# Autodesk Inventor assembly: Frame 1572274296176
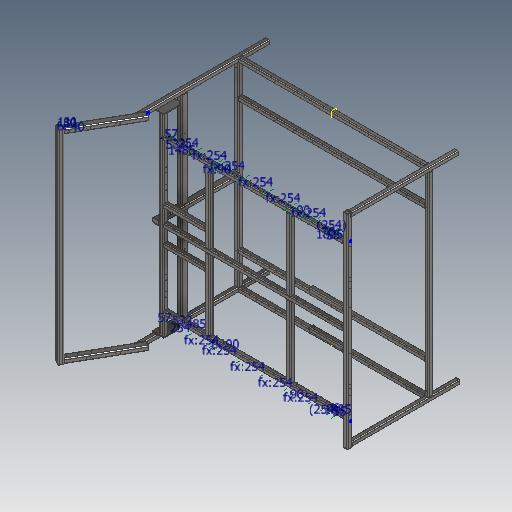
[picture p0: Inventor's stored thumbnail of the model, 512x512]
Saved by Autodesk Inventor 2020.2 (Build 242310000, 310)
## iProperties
_FrameDoc: Frame Assembly
_Version: 15.0.0
Part Number: Frame 1572274296176
Document SubType Name: Baugruppe
Designer: lutzd
Mass: 263385 g
Surface Area: 134163 cm^2
Volume: 33552.3 cm^3
Density: 7.85 g/cm^3
Mass: 263,385 kg
Dimensions: 2170x1958,9x2385 mm
Author: lutzd
Revision Number: -
Title: Frame 1572274296176
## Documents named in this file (26)
- D:\07 - DEMODATEN\OTX 2019 - Dataset - UPDATE - Dez2019\Designs\07-Packing machine\500586R\Frame\Frame 1572274296176.iam
- D:\07 - DEMODATEN\OTX 2019 - Dataset - UPDATE - Dez2019\Designs\07-Packing machine\500586R\Frame\Skeleton 1572274296222.ipt
- D:\07 - DEMODATEN\OTX 2019 - Dataset - UPDATE - Dez2019\Designs\07-Packing machine\500586R\Frame\_DS_FGM_DIN 50 x 50 x 5 1572274297625.ipt
- D:\07 - DEMODATEN\OTX 2019 - Dataset - UPDATE - Dez2019\Designs\07-Packing machine\500586R\Frame\_DS_FGM_DIN 50 x 50 x 5 1572274377820.ipt
- D:\07 - DEMODATEN\OTX 2019 - Dataset - UPDATE - Dez2019\Designs\07-Packing machine\500586R\Frame\_DS_FGM_DIN 70 x 50 x 5 1572274565859.ipt
- D:\07 - DEMODATEN\OTX 2019 - Dataset - UPDATE - Dez2019\Designs\07-Packing machine\500586R\Frame\_DS_FGM_DIN 70 x 50 x 5 1572274889356.ipt
- D:\07 - DEMODATEN\OTX 2019 - Dataset - UPDATE - Dez2019\Designs\07-Packing machine\500586R\Frame\ADSK-014384.ipt
- D:\07 - DEMODATEN\OTX 2019 - Dataset - UPDATE - Dez2019\Designs\07-Packing machine\500586R\Frame\ADSK-014383.ipt
- D:\07 - DEMODATEN\OTX 2019 - Dataset - UPDATE - Dez2019\Designs\07-Packing machine\500586R\Frame\ADSK-014381.ipt
- D:\07 - DEMODATEN\OTX 2019 - Dataset - UPDATE - Dez2019\Designs\07-Packing machine\500586R\Frame\ADSK-014379.ipt
- D:\07 - DEMODATEN\OTX 2019 - Dataset - UPDATE - Dez2019\Designs\07-Packing machine\500586R\Frame\ADSK-014380.ipt
- D:\07 - DEMODATEN\OTX 2019 - Dataset - UPDATE - Dez2019\Designs\07-Packing machine\500586R\Frame\ADSK-014382.ipt
- D:\07 - DEMODATEN\OTX 2019 - Dataset - UPDATE - Dez2019\Designs\07-Packing machine\500586R\Frame\ADSK-014378.ipt
- D:\07 - DEMODATEN\OTX 2019 - Dataset - UPDATE - Dez2019\Designs\07-Packing machine\500586R\Frame\ADSK-014377.ipt
- D:\07 - DEMODATEN\OTX 2019 - Dataset - UPDATE - Dez2019\Designs\07-Packing machine\500586R\Frame\ADSK-014376.ipt
- D:\07 - DEMODATEN\OTX 2019 - Dataset - UPDATE - Dez2019\Designs\07-Packing machine\500586R\Frame\ADSK-014375.ipt
- D:\07 - DEMODATEN\OTX 2019 - Dataset - UPDATE - Dez2019\Designs\07-Packing machine\500586R\Frame\ADSK-014374.ipt
- D:\07 - DEMODATEN\OTX 2019 - Dataset - UPDATE - Dez2019\Designs\07-Packing machine\500586R\Frame\ADSK-014372.ipt
- D:\07 - DEMODATEN\OTX 2019 - Dataset - UPDATE - Dez2019\Designs\07-Packing machine\500586R\Frame\ADSK-014385.ipt
- D:\07 - DEMODATEN\OTX 2019 - Dataset - UPDATE - Dez2019\Designs\07-Packing machine\Parts\ADSK-014388.ipt
- D:\07 - DEMODATEN\OTX 2019 - Dataset - UPDATE - Dez2019\Designs\07-Packing machine\Parts\ADSK-014387.ipt
- D:\07 - DEMODATEN\OTX 2019 - Dataset - UPDATE - Dez2019\Designs\07-Packing machine\Parts\ADSK-014386.ipt
- D:\07 - DEMODATEN\OTX 2019 - Dataset - UPDATE - Dez2019\Designs\07-Packing machine\500586R\Frame\ADSK-014407.ipt
- D:\07 - DEMODATEN\OTX 2019 - Dataset - UPDATE - Dez2019\Designs\07-Packing machine\500586R\Frame\ADSK-014408.ipt
- D:\07 - DEMODATEN\OTX 2019 - Dataset - UPDATE - Dez2019\Designs\07-Packing machine\500586R\Frame\ADSK-014434.ipt
- D:\07 - DEMODATEN\OTX 2019 - Dataset - UPDATE - Dez2019\Designs\07-Packing machine\500586R\Frame\ADSK-014452.ipt
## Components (41 placed, 6 different names)
1. Gestellreferenzmodell
2. DIN 70 x 50 x 5:1
3. DIN 70 x 50 x 5:3
4. DIN 50 x 50 x 5:5
5. DIN 50 x 50 x 5:6
6. DIN 50 x 50 x 5:10
7. DIN 70 x 50 x 5:4
8. DIN 70 x 50 x 5:5
9. Gerundete Ecken (mm) 5 x 60 x 40:5
10. DIN 50 x 50 x 5:9
11. DIN 50 x 50 x 5:23
12. DIN 70 x 50 x 5:6
13. DIN 70 x 50 x 5:7
14. DIN 50 x 50 x 5:1
15. DIN 50 x 50 x 5:2
16. DIN 50 x 50 x 5:3
17. DIN 50 x 50 x 5:4
18. DIN 50 x 50 x 5:7
19. DIN 50 x 50 x 5:12
20. DIN 50 x 50 x 5:8
21. DIN 50 x 50 x 5:14
22. DIN 50 x 50 x 5:11
23. DIN 50 x 50 x 5:15
24. DIN 50 x 50 x 5:16
25. DIN 50 x 50 x 5:17
26. DIN 50 x 50 x 5:20
27. DIN 50 x 50 x 5:21
28. DIN 200 x 10:1
29. DIN 200 x 10:2
30. Gerundete Ecken (mm) 5 x 60 x 40:1
31. Gerundete Ecken (mm) 5 x 60 x 40:2
32. Gerundete Ecken (mm) 5 x 60 x 40:3
33. Gerundete Ecken (mm) 5 x 60 x 40:4
34. Gerundete Ecken (mm) 5 x 40 x 40:1
35. Gerundete Ecken (mm) 5 x 40 x 40:2
36. Gerundete Ecken (mm) 5 x 40 x 40:3
37. Gerundete Ecken (mm) 5 x 40 x 40:4
38. DIN 50 x 50 x 5:18
39. DIN 50 x 50 x 5:22
40. DIN 50 x 50 x 5:24
41. DIN 50 x 50 x 5:25
